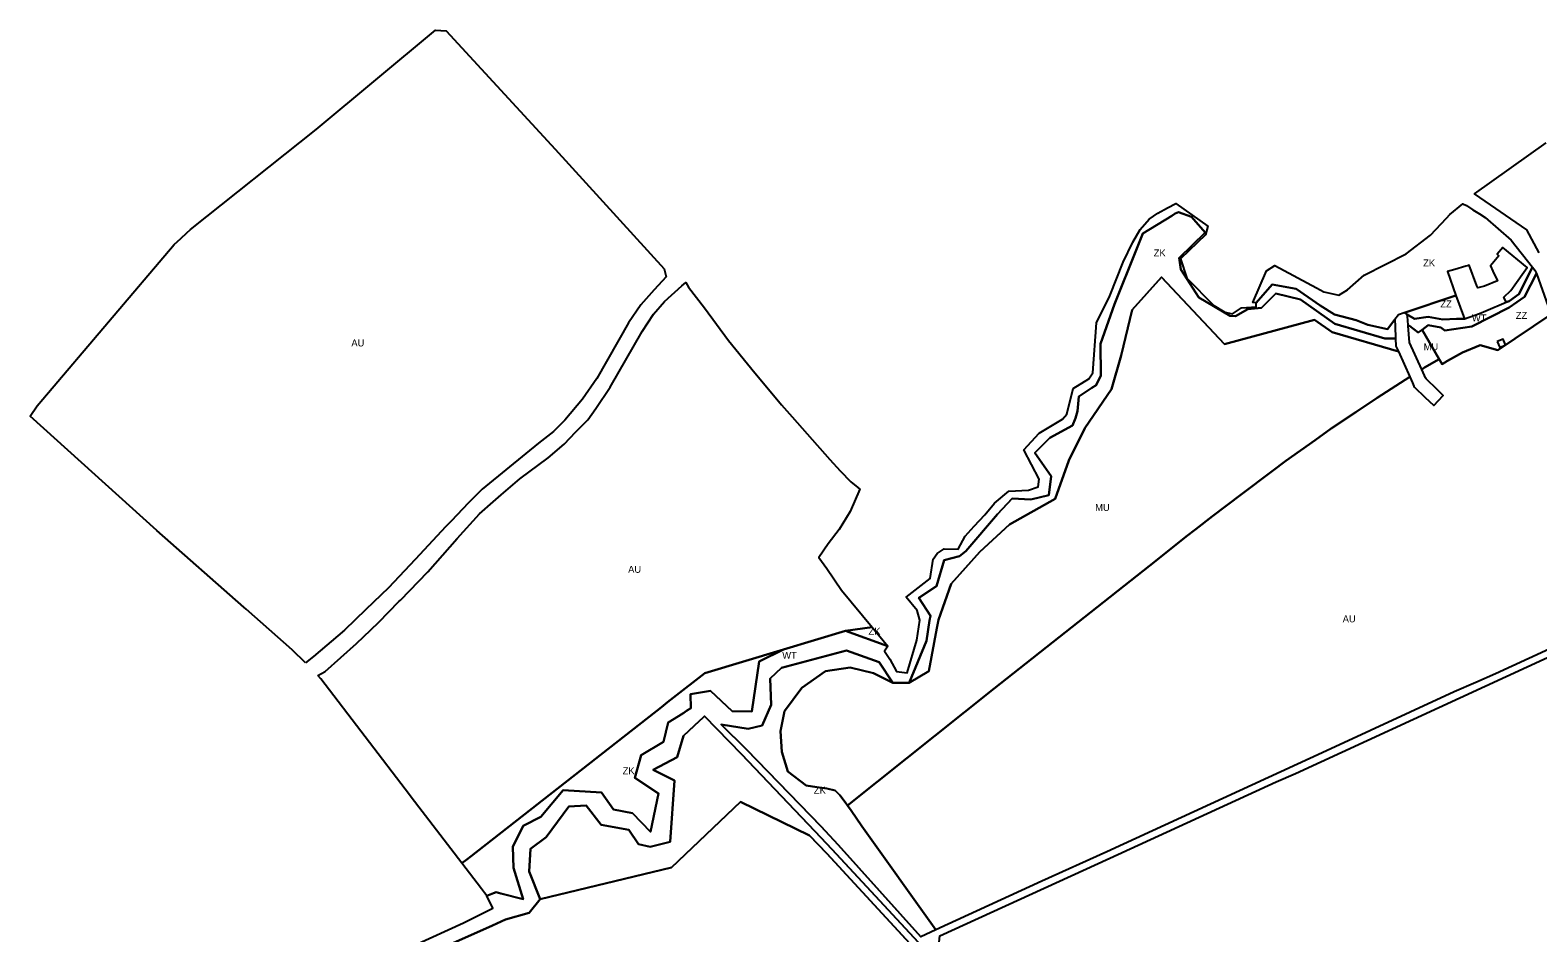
# Model space of a CAD drawing. Extents: x -522079 to -518833, y -1142398 to -1139961.
# Drawn here: x -522079 to -521001, y -1140682 to -1140036 of the extents above; entities that cross this region are included whole.
import ezdxf

# ---------------------------------------------------------------- set-up
doc = ezdxf.new("R2010")
doc.units = 0
for name, color, linetype in [('90640013', 7, 'Continuous'), ('90670013', 7, 'Continuous'), ('90710013', 7, 'Continuous'), ('90750013', 7, 'Continuous'), ('90830013', 7, 'Continuous')]:
    doc.layers.add(name, color=color, linetype=linetype)

msp = doc.modelspace()

# ---------------------------------------------------------------- linework, layer by layer
at = {"layer": '90640013'}
for points in [[(-521804.78, -1140690.88), (-521769.34, -1140674.65), (-521748.38, -1140664.24), (-521752.49, -1140655.36), (-521747.72, -1140653.54), (-521745.77, -1140652.8), (-521742.5, -1140653.65), (-521726.67, -1140657.74), (-521733.38, -1140635.33), (-521734.01, -1140620.28), (-521726.52, -1140605.2), (-521713.89, -1140598.84), (-521698, -1140579.74), (-521670.5, -1140581.53), (-521661.89, -1140593.5), (-521648.43, -1140596.09), (-521635.54, -1140609.6), (-521629.87, -1140582.04), (-521646.65, -1140571), (-521642.26, -1140554.66), (-521626.2, -1140545.21), (-521622.75, -1140531.26), (-521615.57, -1140526.74), (-521611.69, -1140524.3), (-521609.78, -1140523.1), (-521606.6, -1140521.1), (-521606.9, -1140511.13), (-521592.51, -1140508.64), (-521577.07, -1140523.11), (-521562.91, -1140523.45), (-521557.78, -1140487.71), (-521540.23, -1140479.04), (-521496.06, -1140465.78), (-521465.61, -1140476.61), (-521468.11, -1140480.32), (-521464.21, -1140485.93), (-521459.62, -1140494.93), (-521451.98, -1140495.75), (-521445.06, -1140472.47), (-521442.88, -1140458.09), (-521444.82, -1140451.17), (-521452.48, -1140441.66), (-521435.44, -1140428.3), (-521433.21, -1140414.4), (-521430.32, -1140410.33), (-521425.52, -1140407.15), (-521415.37, -1140407.41), (-521410.38, -1140398.05), (-521403.86, -1140390.75), (-521396.32, -1140382.62), (-521389.35, -1140374.32), (-521379.07, -1140365.7), (-521365.2, -1140365.12), (-521358.18, -1140362.8), (-521357.5, -1140357.21), (-521368.43, -1140336.25), (-521357.43, -1140324.38), (-521340.77, -1140314.23), (-521337.76, -1140310.68), (-521333.16, -1140292.26), (-521321.89, -1140285.5), (-521319.14, -1140281.01), (-521316.46, -1140245.31), (-521306.79, -1140226.13), (-521297.37, -1140201.85), (-521290.54, -1140187.61), (-521285.21, -1140178.6), (-521278.81, -1140171.17), (-521272.67, -1140166.78), (-521265.75, -1140163.05), (-521259.67, -1140159.99), (-521236.81, -1140176.19), (-521238.42, -1140182.36), (-521256.3, -1140199.5), (-521251.89, -1140213.49), (-521232.49, -1140232.94), (-521224.62, -1140237.78), (-521219.26, -1140238.96), (-521212.75, -1140234.73), (-521205.52, -1140234.19), (-521202.32, -1140233.95), (-521202.15, -1140231.14), (-521190.8, -1140217.9), (-521173.55, -1140221.12), (-521156.43, -1140232.87), (-521146.28, -1140239.39), (-521130.62, -1140243.41), (-521122.43, -1140246.78), (-521108.36, -1140249.87), (-521102.93, -1140242.86), (-521102.76, -1140247.73), (-521102.44, -1140256.49), (-521110.27, -1140256.62), (-521146.04, -1140246.18), (-521170.61, -1140228.65), (-521188.13, -1140224.34), (-521198.5, -1140234.71), (-521205.87, -1140235.43), (-521208.19, -1140235.66), (-521217.02, -1140240.66), (-521221.12, -1140240.34), (-521243.23, -1140227.2), (-521256.03, -1140207.29), (-521257.36, -1140198.93), (-521238.63, -1140180.63), (-521248.42, -1140169.45), (-521257.73, -1140166.05), (-521260.08, -1140167.19), (-521262.49, -1140168.67), (-521283.26, -1140181.41), (-521288.02, -1140193.37), (-521303.57, -1140232.09), (-521313.53, -1140260.28), (-521313.45, -1140283.14), (-521316.7, -1140289.98), (-521319.77, -1140291.98), (-521329.18, -1140298.1), (-521329.93, -1140308.65), (-521331.35, -1140313.68), (-521333.68, -1140318.76), (-521349.83, -1140327.64), (-521354.5, -1140332.33), (-521360.62, -1140338.49), (-521348.98, -1140355.15), (-521350.48, -1140368.68), (-521363.37, -1140371.78), (-521376.68, -1140371.11), (-521387.23, -1140382.25), (-521409.97, -1140408.74), (-521414.4, -1140412.25), (-521425.29, -1140415.18), (-521430.97, -1140433.67), (-521443.44, -1140442.21), (-521435.3, -1140455), (-521435.8, -1140458.35), (-521437.98, -1140472.83), (-521450.52, -1140503.04), (-521462.16, -1140502.96), (-521471.95, -1140488.22), (-521495.23, -1140479.84), (-521541.79, -1140492.15), (-521549.91, -1140499.85), (-521549.24, -1140518.67), (-521555.6, -1140533.49), (-521565.66, -1140535.94), (-521584.91, -1140532.83), (-521566.82, -1140550.59), (-521513.48, -1140605.69), (-521510.5, -1140608.85), (-521501.14, -1140618.78), (-521441.99, -1140684.63)], [(-521379.23, -1140758.51), (-521505.44, -1140622.18), (-521517.85, -1140609.14), (-521570.34, -1140553.98), (-521596.8, -1140526.87), (-521598.04, -1140528.01), (-521600.31, -1140530.11), (-521611.96, -1140540.86), (-521616.47, -1140556.14), (-521633.5, -1140565.29), (-521618.3, -1140572.85), (-521621.47, -1140616.67), (-521635.78, -1140620.38), (-521643.99, -1140618.34), (-521650.96, -1140608.19), (-521670.89, -1140604.59), (-521681.44, -1140590.68), (-521693.94, -1140591.41), (-521710.1, -1140613.29), (-521721.28, -1140621.72), (-521722.39, -1140637.91), (-521714.47, -1140657.84), (-521722.24, -1140667.6), (-521739.27, -1140672.34), (-521748.53, -1140676.5), (-521785.36, -1140693.05)]]:
    msp.add_lwpolyline(points, dxfattribs=at)
msp.add_lwpolyline([(-521053.25, -1140242.58), (-521042.48, -1140238.76), (-521037.86, -1140236.76), (-521023.4, -1140230.68), (-521021.33, -1140229.82), (-521014.41, -1140224.73), (-521004.56, -1140205.45), (-521002.93, -1140207.73), (-521001.72, -1140210.08), (-521010.26, -1140226.65), (-521021.33, -1140234.46), (-521047.85, -1140248.01), (-521067.28, -1140250.75), (-521070.02, -1140248.6), (-521079.08, -1140247.03), (-521083.46, -1140250.25), (-521086.36, -1140252.38), (-521092.43, -1140247.55), (-521093.43, -1140247.58), (-521093.8, -1140243.17), (-521094.12, -1140239.48), (-521088.86, -1140242.57), (-521079.19, -1140241.03), (-521068.77, -1140242.91), (-521058.99, -1140242.45)], close=True, dxfattribs=at)
at = {"layer": '90670013'}
for points in [[(-521071.39, -1140271.24), (-521083.46, -1140250.25), (-521079.08, -1140247.03), (-521070.02, -1140248.6), (-521067.28, -1140250.75), (-521047.85, -1140248.01), (-521021.33, -1140234.46), (-521010.26, -1140226.65), (-521001.72, -1140210.08), (-520993.36, -1140233.77), (-520991.34, -1140239.5), (-521029.36, -1140265.01), (-521042, -1140261.25), (-521054.61, -1140266.48), (-521065.28, -1140272.43), (-521069.26, -1140274.95)], [(-521053.25, -1140242.58), (-521058.99, -1140242.45), (-521068.77, -1140242.91), (-521079.19, -1140241.03), (-521088.86, -1140242.57), (-521094.12, -1140239.48), (-521096.26, -1140238.22), (-521059.29, -1140225.79)], [(-521029.71, -1140258.76), (-521027.96, -1140262.97), (-521023.8, -1140261.15), (-521025.45, -1140257.06)]]:
    msp.add_lwpolyline(points, close=True, dxfattribs=at)
at = {"layer": '90710013'}
for points in [[(-520999.73, -1140195.29), (-521008.55, -1140178.79), (-521045.99, -1140153.16), (-520994.7, -1140116.62)], [(-521424.45, -1140717.21), (-521509.24, -1140625.15), (-521521.75, -1140612.22), (-521571.05, -1140588.16), (-521620.49, -1140635.2), (-521714.47, -1140657.84), (-521722.39, -1140637.91), (-521721.28, -1140621.72), (-521710.1, -1140613.29), (-521693.94, -1140591.41), (-521681.44, -1140590.68), (-521670.89, -1140604.59), (-521650.96, -1140608.19), (-521643.99, -1140618.34), (-521635.78, -1140620.38), (-521621.47, -1140616.67), (-521618.3, -1140572.85), (-521633.5, -1140565.29), (-521616.47, -1140556.14), (-521611.96, -1140540.86), (-521600.31, -1140530.11), (-521598.04, -1140528.01), (-521596.8, -1140526.87), (-521570.34, -1140553.98), (-521517.85, -1140609.14), (-521505.44, -1140622.18), (-521379.23, -1140758.51)]]:
    msp.add_lwpolyline(points, dxfattribs=at)
for points in [[(-521102.93, -1140242.86), (-521108.36, -1140249.87), (-521122.43, -1140246.78), (-521130.62, -1140243.41), (-521146.28, -1140239.39), (-521156.43, -1140232.87), (-521173.55, -1140221.12), (-521190.8, -1140217.9), (-521202.15, -1140231.14), (-521204.62, -1140230.71), (-521194.92, -1140208.09), (-521188.9, -1140204.31), (-521159.02, -1140220.32), (-521153.92, -1140223.1), (-521142.98, -1140225.64), (-521136.78, -1140221.72), (-521124.89, -1140211.23), (-521094.81, -1140196.05), (-521077.51, -1140182.69), (-521066.01, -1140170.35), (-521063.7, -1140167.77), (-521054.36, -1140160.13), (-521051.86, -1140161.45), (-521047.19, -1140164.44), (-521042.52, -1140167.42), (-521038.45, -1140170.03), (-521019.82, -1140186.27), (-521004.56, -1140205.45), (-521014.41, -1140224.73), (-521021.33, -1140229.82), (-521023.4, -1140230.68), (-521024.94, -1140227.06), (-521019.95, -1140222.33), (-521011.89, -1140210.69), (-521008.43, -1140205.69), (-521025.79, -1140191.41), (-521029.89, -1140196.26), (-521028.73, -1140197.48), (-521034.61, -1140204.63), (-521032.9, -1140208.45), (-521029.59, -1140215.24), (-521038.87, -1140219.06), (-521039.84, -1140219.26), (-521043.73, -1140220.34), (-521044.31, -1140218.8), (-521049.86, -1140204.08), (-521050.38, -1140204.23), (-521052.23, -1140204.77), (-521060.17, -1140207.15), (-521065.43, -1140208.69), (-521059.29, -1140225.79), (-521096.26, -1140238.22), (-521100.42, -1140239.62)], [(-521450.52, -1140503.04), (-521437.98, -1140472.83), (-521435.8, -1140458.35), (-521435.3, -1140455), (-521443.44, -1140442.21), (-521430.97, -1140433.67), (-521425.29, -1140415.18), (-521414.4, -1140412.25), (-521409.97, -1140408.74), (-521387.23, -1140382.25), (-521376.68, -1140371.11), (-521363.37, -1140371.78), (-521350.48, -1140368.68), (-521348.98, -1140355.15), (-521360.62, -1140338.49), (-521354.5, -1140332.33), (-521349.83, -1140327.64), (-521333.68, -1140318.76), (-521331.35, -1140313.68), (-521329.93, -1140308.65), (-521329.18, -1140298.1), (-521319.77, -1140291.98), (-521316.7, -1140289.98), (-521313.45, -1140283.14), (-521313.53, -1140260.28), (-521303.57, -1140232.09), (-521288.02, -1140193.37), (-521283.26, -1140181.41), (-521262.49, -1140168.67), (-521260.08, -1140167.19), (-521257.73, -1140166.05), (-521248.42, -1140169.45), (-521238.63, -1140180.63), (-521257.36, -1140198.93), (-521256.03, -1140207.29), (-521243.23, -1140227.2), (-521221.12, -1140240.34), (-521217.02, -1140240.66), (-521208.19, -1140235.66), (-521205.87, -1140235.43), (-521198.5, -1140234.71), (-521188.13, -1140224.34), (-521170.61, -1140228.65), (-521146.04, -1140246.18), (-521110.27, -1140256.62), (-521102.44, -1140256.49), (-521102.24, -1140261.94), (-521100.5, -1140265.83), (-521147.75, -1140252.04), (-521160.59, -1140243.23), (-521224.97, -1140260.52), (-521269.84, -1140212.73), (-521291.01, -1140236.12), (-521298.91, -1140268.76), (-521305.66, -1140292.85), (-521324.74, -1140320.75), (-521336.24, -1140343.91), (-521346.04, -1140371.4), (-521378.73, -1140389.63), (-521399.96, -1140409.23), (-521420.52, -1140431.99), (-521429.44, -1140457.98), (-521430.55, -1140463.89), (-521436.3, -1140494.58)], [(-521465.61, -1140476.61), (-521496.06, -1140465.78), (-521476.87, -1140463.06)], [(-521770.53, -1140631.96), (-521766.84, -1140629.25), (-521763.73, -1140626.86), (-521627.73, -1140520.35), (-521623.29, -1140516.88), (-521619, -1140513.52), (-521596.59, -1140495.96), (-521540.23, -1140479.04), (-521557.78, -1140487.71), (-521562.91, -1140523.45), (-521577.07, -1140523.11), (-521592.51, -1140508.64), (-521606.9, -1140511.13), (-521606.6, -1140521.1), (-521609.78, -1140523.1), (-521611.69, -1140524.3), (-521615.57, -1140526.74), (-521622.75, -1140531.26), (-521626.2, -1140545.21), (-521642.26, -1140554.66), (-521646.65, -1140571), (-521629.87, -1140582.04), (-521635.54, -1140609.6), (-521648.43, -1140596.09), (-521661.89, -1140593.5), (-521670.5, -1140581.53), (-521698, -1140579.74), (-521713.89, -1140598.84), (-521726.52, -1140605.2), (-521734.01, -1140620.28), (-521733.38, -1140635.33), (-521726.67, -1140657.74), (-521742.5, -1140653.65), (-521745.77, -1140652.8), (-521747.72, -1140653.54), (-521752.49, -1140655.36), (-521754.23, -1140653.26), (-521756.45, -1140650.36)], [(-521462.16, -1140502.96), (-521476.06, -1140495.98), (-521492.65, -1140492.08), (-521510.34, -1140494.68), (-521527.29, -1140506.41), (-521539.58, -1140523.18), (-521542.41, -1140537.54), (-521541.63, -1140552.23), (-521537.25, -1140566.46), (-521524.24, -1140576.46), (-521516.38, -1140577.7), (-521509.23, -1140578.46), (-521503.43, -1140580.09), (-521499.98, -1140583.25), (-521496.32, -1140588.3), (-521494.62, -1140590.69), (-521492.01, -1140594.38), (-521484.19, -1140605.4), (-521431.42, -1140679.77), (-521441.99, -1140684.63), (-521501.14, -1140618.78), (-521510.5, -1140608.85), (-521513.48, -1140605.69), (-521566.82, -1140550.59), (-521584.91, -1140532.83), (-521565.66, -1140535.94), (-521555.6, -1140533.49), (-521549.24, -1140518.67), (-521549.91, -1140499.85), (-521541.79, -1140492.15), (-521495.23, -1140479.84), (-521471.95, -1140488.22)]]:
    msp.add_lwpolyline(points, close=True, dxfattribs=at)
at = {"layer": '90750013'}
for points in [[(-521882.18, -1140488.56), (-521891.73, -1140479.43), (-521924.65, -1140450.32), (-521926.43, -1140448.75), (-521988.52, -1140393.86), (-522079.24, -1140312.2), (-522074.19, -1140304.73), (-522070.23, -1140300.06), (-521976.31, -1140189.41), (-521971.46, -1140184.95), (-521967.11, -1140180.95), (-521964.54, -1140178.59), (-521874.73, -1140107.13), (-521789.25, -1140035.92), (-521781.62, -1140036.36), (-521703.78, -1140121.15), (-521625.65, -1140206.61), (-521624.31, -1140212.38), (-521632.85, -1140221.77), (-521642.31, -1140232.52), (-521651.12, -1140245.38), (-521673.96, -1140285.19), (-521684.15, -1140299.89), (-521696.71, -1140315.1), (-521704.79, -1140323.18), (-521715.5, -1140331.4), (-521736.25, -1140348.4), (-521755.99, -1140364.38), (-521765.79, -1140374.26), (-521778.1, -1140387.34), (-521781.95, -1140390.97), (-521803.88, -1140414.74), (-521822.79, -1140434.86), (-521839, -1140450.48), (-521854.3, -1140465.27), (-521876.66, -1140484.09)], [(-521873.47, -1140497.6), (-521868.24, -1140494.75), (-521845.84, -1140474.71), (-521835.62, -1140465.09), (-521829.77, -1140459.58), (-521815.4, -1140444.86), (-521814.39, -1140443.83), (-521794.87, -1140423.48), (-521773.82, -1140399.6), (-521757.78, -1140381.98), (-521747.91, -1140373.33), (-521742.3, -1140368.5), (-521728.93, -1140357.06), (-521708.67, -1140341.98), (-521697.12, -1140332.11), (-521688.85, -1140323.27), (-521680.22, -1140314.66), (-521674.58, -1140306.67), (-521664.44, -1140291.34), (-521641.46, -1140251.62), (-521633.25, -1140239.25), (-521625.36, -1140230.13), (-521613.09, -1140218.9), (-521610.22, -1140216.5), (-521608.33, -1140219.87), (-521596.95, -1140234.61), (-521579.62, -1140257.92), (-521560.73, -1140281.01), (-521544.01, -1140301.33), (-521541.69, -1140303.97), (-521534.06, -1140312.64), (-521523.43, -1140324.72), (-521507.29, -1140343.05), (-521499.72, -1140351.14), (-521492.09, -1140359.13), (-521487.26, -1140363.09), (-521485.71, -1140364.38), (-521492.65, -1140380.39), (-521500.52, -1140393.33), (-521508.32, -1140403.51), (-521515.07, -1140413.37), (-521509.46, -1140421.2), (-521498.88, -1140436.59), (-521476.87, -1140463.06), (-521496.06, -1140465.78), (-521540.23, -1140479.04), (-521596.59, -1140495.96), (-521619, -1140513.52), (-521623.29, -1140516.88), (-521627.73, -1140520.35), (-521763.73, -1140626.86), (-521766.84, -1140629.25), (-521770.53, -1140631.96), (-521806.71, -1140584.66), (-521807.95, -1140583.04), (-521871.3, -1140500.06)]]:
    msp.add_lwpolyline(points, close=True, dxfattribs=at)
for points in [[(-520911.89, -1140441.66), (-521031.07, -1140496.4), (-521045.09, -1140502.65), (-521060.49, -1140509.3), (-521152, -1140551.52), (-521309.07, -1140623.96), (-521355.48, -1140644.9), (-521431.42, -1140679.77), (-521484.19, -1140605.4), (-521492.01, -1140594.38), (-521494.62, -1140590.69), (-521389.53, -1140507.12), (-521274.04, -1140415.55), (-521252.22, -1140398.25), (-521245.45, -1140392.88), (-521233.39, -1140383.74), (-521212.85, -1140368.17), (-521190.73, -1140351.49), (-521181.05, -1140344.19), (-521160.13, -1140329.24), (-521148.51, -1140320.94), (-521130.86, -1140309.33), (-521115.76, -1140299), (-521092.32, -1140284.11), (-521090.43, -1140288.34), (-521089.34, -1140290.78), (-521089.05, -1140291.44), (-521081.54, -1140298.53), (-521075.22, -1140304.5), (-521068.35, -1140297.23), (-521072.76, -1140293.07), (-521080.73, -1140285.54), (-521081.11, -1140284.7), (-521081.89, -1140282.94), (-521083.79, -1140278.7), (-521081.77, -1140277.41), (-521071.39, -1140271.24), (-521069.26, -1140274.95), (-521065.28, -1140272.43), (-521054.61, -1140266.48), (-521042, -1140261.25), (-521029.36, -1140265.01), (-520991.34, -1140239.5)], [(-520989.26, -1140956.04), (-521082.3, -1140995.42), (-521133.42, -1140928.49), (-521179.82, -1140867.68), (-521217.11, -1140828.01), (-521234.98, -1140825.42), (-521290.3, -1140823.03), (-521300.72, -1140819.47), (-521372.2, -1140749.84), (-521386.59, -1140734.32), (-521428.9, -1140688.4), (-521428.47, -1140683.93), (-521306.81, -1140628.37), (-521187.8, -1140573.75), (-521174.07, -1140567.72), (-521038.29, -1140505.39), (-520909.31, -1140446.06)], [(-521785.36, -1140693.05), (-521748.53, -1140676.5), (-521739.27, -1140672.34), (-521722.24, -1140667.6), (-521714.47, -1140657.84), (-521620.49, -1140635.2), (-521571.05, -1140588.16), (-521521.75, -1140612.22), (-521509.24, -1140625.15), (-521424.45, -1140717.21)]]:
    msp.add_lwpolyline(points, dxfattribs=at)
at = {"layer": '90830013'}
for points in [[(-521450.52, -1140503.04), (-521436.3, -1140494.58), (-521430.55, -1140463.89), (-521429.44, -1140457.98), (-521420.52, -1140431.99), (-521399.96, -1140409.23), (-521378.73, -1140389.63), (-521346.04, -1140371.4), (-521336.24, -1140343.91), (-521324.74, -1140320.75), (-521305.66, -1140292.85), (-521298.91, -1140268.76), (-521291.01, -1140236.12), (-521269.84, -1140212.73), (-521224.97, -1140260.52), (-521160.59, -1140243.23), (-521147.75, -1140252.04), (-521100.5, -1140265.83), (-521092.32, -1140284.11), (-521115.76, -1140299), (-521130.86, -1140309.33), (-521148.51, -1140320.94), (-521160.13, -1140329.24), (-521181.05, -1140344.19), (-521190.73, -1140351.49), (-521212.85, -1140368.17), (-521233.39, -1140383.74), (-521245.45, -1140392.88), (-521252.22, -1140398.25), (-521274.04, -1140415.55), (-521389.53, -1140507.12), (-521494.62, -1140590.69), (-521496.32, -1140588.3), (-521499.98, -1140583.25), (-521503.43, -1140580.09), (-521509.23, -1140578.46), (-521516.38, -1140577.7), (-521524.24, -1140576.46), (-521537.25, -1140566.46), (-521541.63, -1140552.23), (-521542.41, -1140537.54), (-521539.58, -1140523.18), (-521527.29, -1140506.41), (-521510.34, -1140494.68), (-521492.65, -1140492.08), (-521476.06, -1140495.98), (-521462.16, -1140502.96)], [(-521071.39, -1140271.24), (-521081.77, -1140277.41), (-521083.79, -1140278.7), (-521092.42, -1140259.41), (-521093.43, -1140247.58), (-521092.43, -1140247.55), (-521086.36, -1140252.38), (-521083.46, -1140250.25)]]:
    msp.add_lwpolyline(points, close=True, dxfattribs=at)

# ---------------------------------------------------------------- texts
at = {"layer": '90640013'}
for p in [(-521047.92, -1140244.355), (-521541.23, -1140485.768)]:
    msp.add_text('WT', height=5, rotation=360, dxfattribs=at).set_placement(p)
at = {"layer": '90670013'}
for p in [(-521070.48, -1140234.35), (-521016.464, -1140242.515)]:
    msp.add_text('ZZ', height=5, rotation=360, dxfattribs=at).set_placement(p)
at = {"layer": '90710013'}
for rotation, p in [(0, (-521275.51, -1140197.825)), (0, (-521082.771, -1140205)), (0, (-521479.513, -1140468.483)), (0, (-521655.38, -1140568.379)), (360, (-521518.637, -1140582.235))]:
    msp.add_text('ZK', height=5, rotation=rotation, dxfattribs=at).set_placement(p)
at = {"layer": '90750013'}
for p in [(-521849.461, -1140262.24), (-521651.483, -1140424.23), (-521140.333, -1140459.635)]:
    msp.add_text('AU', height=5, rotation=360, dxfattribs=at).set_placement(p)
at = {"layer": '90830013'}
for p in [(-521082.41, -1140264.947), (-521317.365, -1140379.934)]:
    msp.add_text('MU', height=5, rotation=360, dxfattribs=at).set_placement(p)

doc.saveas('drawing.dxf')
